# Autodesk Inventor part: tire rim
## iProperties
Author: vincent molino
Shininess: 20.0
Angle Display Precision: 2
Document Length Units: 11272
Document Angle Units: 11286
Document Time Units: 11279
Document Mass Units: 11290
Document Length Units Precision: 3
Document Angle Units Precision: 2
Compacted: True
PropertySet Name: _Private Model Information
Created: 2002-01
Part Number: tire rim
Document SubType Name: Modeling
Designer: vincent molino
Control State: 0
Master: False
Checked Out: False
PropertySet Name: Design Tracking Control
Density: 0.0
Volumn: 0.0
Area: 0.0
PropertySet Name: Model Information
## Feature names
1. Revolution1
2. Mirror1
3. Hole1
